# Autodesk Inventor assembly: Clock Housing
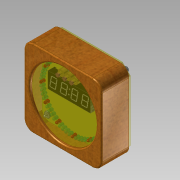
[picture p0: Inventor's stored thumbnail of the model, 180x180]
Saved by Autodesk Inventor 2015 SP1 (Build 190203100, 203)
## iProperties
Created: 2015-05
Part Number: Clock Housing
Document SubType Name: Assembly
Designer: kazys
Author: kazys
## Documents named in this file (11)
- C:\Users\kazys\Documents\Inventor\Clock\Clock Housing.iam
- C:\Users\kazys\Documents\Inventor\Clock\Clock Housing.ipt
- C:\Users\kazys\Documents\Inventor\Clock\Clock window.ipt
- C:\Users\kazys\Documents\Inventor\Clock\Clock back.ipt
- C:\Users\kazys\Documents\Inventor\Clock\spacer mf.ipt
- C:\Users\kazys\Documents\Inventor\Clock\Button.ipt
- C:\Users\kazys\Documents\Inventor\Clock\USB-Mini B_Cable.ipt
- C:\Users\kazys\Documents\Inventor\Clock\Clock Board Assy EC1204B.iam
- C:\Users\kazys\Documents\Inventor\Content Center Files\R2015\en-US\ANSI B18.6.3(25)\ANSI B18.6.3 - 4-40 UNC - 0.25(5).ipt
- C:\Users\kazys\Documents\Inventor\Content Center Files\R2015\en-US\ANSI B18.6.3(36)\ANSI B18.6.3 - 4 - 40(2).ipt
- C:\Users\kazys\Documents\Inventor\Content Center Files\R2015\en-US\ANSI B18.6.5M(21)\ANSI B18.6.5M - 2.9x1 x 8(22).ipt
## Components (24 placed, 10 different names)
1. Clock Housing:1 — Flush:2, Mate:1, Mate:2, Mate:3, Flush:3
2. Clock window:1 — Mate:1, Mate:2, Mate:3
3. Clock back:1 — Flush:3, Insert:8, Insert:9, Insert:10, Insert:11, Insert:16, Insert:17, Insert:18
4. spacer mf:1
5. spacer mf:2
6. spacer mf:3
7. spacer mf:4
8. Button:1 — Insert:7
9. Button:2 — Insert:6
10. Button:3 — Insert:5
11. USB-Mini B_Cable:1
12. Clock Board Assy EC1204B:1 [sub-assembly] — Insert:5, Insert:6, Insert:7, Mate:5, Mate:7, Mate:9, Mate:11
13. Cross Recessed Pan Head Machine Screw - Type IA - Inch No. 4 - 40 - 1/4:1 — Insert:8
14. Cross Recessed Pan Head Machine Screw - Type IA - Inch No. 4 - 40 - 1/4:2 — Insert:9
15. Cross Recessed Pan Head Machine Screw - Type IA - Inch No. 4 - 40 - 1/4:3 — Insert:10
16. Cross Recessed Pan Head Machine Screw - Type IA - Inch No. 4 - 40 - 1/4:4 — Insert:11
17. Hex Machine Screw Nut - Inch 4 - 40:1 — Mate:5
18. Hex Machine Screw Nut - Inch 4 - 40:2 — Mate:7
19. Hex Machine Screw Nut - Inch 4 - 40:3 — Mate:9
20. Hex Machine Screw Nut - Inch 4 - 40:4 — Mate:11
21. Cross Recessed Pan Head Tapping Screw - Type BT - Type IA - Metric 2.9x1 x 8:1
22. Cross Recessed Pan Head Tapping Screw - Type BT - Type IA - Metric 2.9x1 x 8:2 — Insert:16
23. Cross Recessed Pan Head Tapping Screw - Type BT - Type IA - Metric 2.9x1 x 8:3 — Insert:18
24. Cross Recessed Pan Head Tapping Screw - Type BT - Type IA - Metric 2.9x1 x 8:4 — Insert:17
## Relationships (19: Insert 10, Mate 7, Flush 2)
- Flush:2: Clock Housing:1
- Mate:1: Clock Housing:1 ↔ Clock window:1
- Mate:2: Clock Housing:1 ↔ Clock window:1
- Mate:3: Clock Housing:1 ↔ Clock window:1
- Flush:3: Clock Housing:1 ↔ Clock back:1
- Insert:5: Button:3 ↔ Clock Board Assy EC1204B:1
- Insert:6: Button:2 ↔ Clock Board Assy EC1204B:1
- Insert:7: Button:1 ↔ Clock Board Assy EC1204B:1
- Insert:8: Clock back:1 ↔ Cross Recessed Pan Head Machine Screw - Type IA - Inch No. 4 - 40 - 1/4:1
- Insert:9: Clock back:1 ↔ Cross Recessed Pan Head Machine Screw - Type IA - Inch No. 4 - 40 - 1/4:2
- Insert:10: Clock back:1 ↔ Cross Recessed Pan Head Machine Screw - Type IA - Inch No. 4 - 40 - 1/4:3
- Insert:11: Clock back:1 ↔ Cross Recessed Pan Head Machine Screw - Type IA - Inch No. 4 - 40 - 1/4:4
- Mate:5: Clock Board Assy EC1204B:1 ↔ Hex Machine Screw Nut - Inch 4 - 40:1
- Mate:7: Clock Board Assy EC1204B:1 ↔ Hex Machine Screw Nut - Inch 4 - 40:2
- Mate:9: Clock Board Assy EC1204B:1 ↔ Hex Machine Screw Nut - Inch 4 - 40:3
- Mate:11: Clock Board Assy EC1204B:1 ↔ Hex Machine Screw Nut - Inch 4 - 40:4
- Insert:16: Clock back:1 ↔ Cross Recessed Pan Head Tapping Screw - Type BT - Type IA - Metric 2.9x1 x 8:2
- Insert:17: Clock back:1 ↔ Cross Recessed Pan Head Tapping Screw - Type BT - Type IA - Metric 2.9x1 x 8:4
- Insert:18: Clock back:1 ↔ Cross Recessed Pan Head Tapping Screw - Type BT - Type IA - Metric 2.9x1 x 8:3
